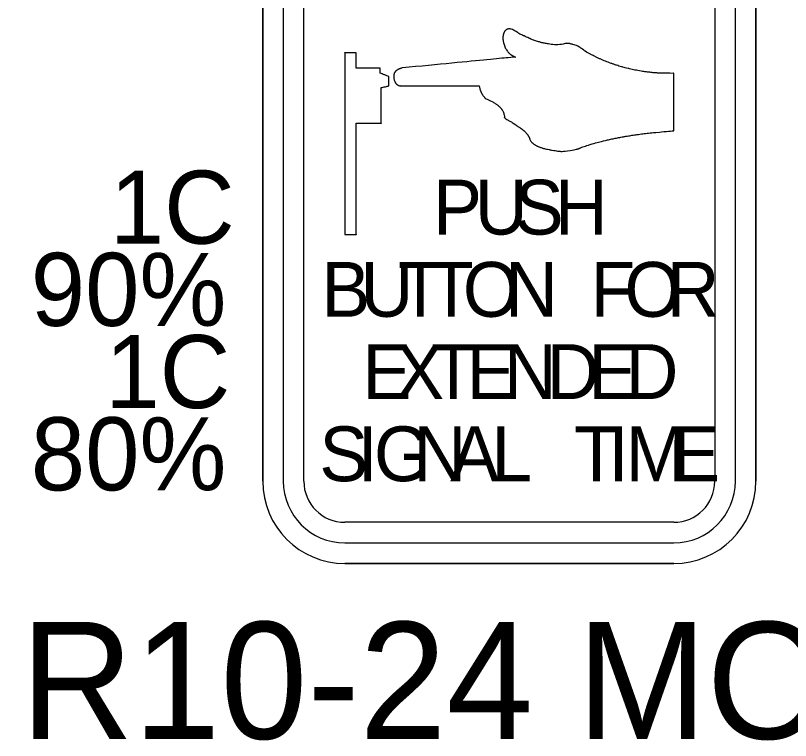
# Model space of a CAD drawing. Extents: x 99982 to 100176, y 99905 to 100011.
# Drawn here: x 100049.2714 to 100049.7487, y 99915.0774 to 99915.5238 of the extents above; entities that cross this region are included whole.
import ezdxf

# ---------------------------------------------------------------- set-up
doc = ezdxf.new("R2010")
doc.units = 0
doc.layers.add('TR_SN_ConstructionSigns', color=7, linetype='Continuous')

msp = doc.modelspace()

# ---------------------------------------------------------------- linework, layer by layer
at = {"layer": 'TR_SN_ConstructionSigns'}
for p, q in [((100049.42363, 99915.23704), (100049.42363, 99915.64204)), ((100049.42363, 99915.64204), (100049.42363, 99915.23704)), ((100049.42363, 99915.64204), (100049.42363, 99915.23704)), ((100049.43628, 99915.64204), (100049.43628, 99915.23704)), ((100049.44894, 99915.23704), (100049.44894, 99915.64204)), ((100049.70207, 99915.64204), (100049.70207, 99915.23704)), ((100049.71472, 99915.23704), (100049.71472, 99915.64204)), ((100049.72738, 99915.64204), (100049.72738, 99915.23704)), ((100049.72738, 99915.23704), (100049.72738, 99915.64204)), ((100049.72738, 99915.23704), (100049.72738, 99915.64204)), ((100049.67675, 99915.21173), (100049.47425, 99915.21173)), ((100049.47425, 99915.19907), (100049.67675, 99915.19907)), ((100049.67675, 99915.18641), (100049.47425, 99915.18641)), ((100049.47425, 99915.18641), (100049.67675, 99915.18641)), ((100049.47425, 99915.18641), (100049.67675, 99915.18641))]:
    msp.add_line(p, q, dxfattribs=at)
for centre, radius, start, end in [((100049.47425, 99915.23704), 0.05063, 180, 270), ((100049.47425, 99915.23704), 0.05063, 180, 270), ((100049.47425, 99915.23704), 0.05063, 180, 270), ((100049.47425, 99915.23704), 0.03797, 180, 270), ((100049.47425, 99915.23704), 0.02531, 180, 270), ((100049.67675, 99915.23704), 0.05063, 270, 0), ((100049.67675, 99915.23704), 0.05063, 270, 0), ((100049.67675, 99915.23704), 0.03797, 270, 0), ((100049.67675, 99915.23704), 0.02531, 270, 0), ((100049.67675, 99915.23704), 0.05063, 270, 0)]:
    msp.add_arc(centre, radius, start, end, dxfattribs=at)
for points, degree in [([(100049.5728, 99915.51427), (100049.5728, 99915.51427), (100049.57265, 99915.51408), (100049.57249, 99915.51386), (100049.5724, 99915.51369), (100049.5724, 99915.51369)], 3), ([(100049.57333, 99915.51481), (100049.57333, 99915.51481), (100049.57315, 99915.51466), (100049.57295, 99915.51446), (100049.5728, 99915.51427), (100049.5728, 99915.51427)], 3), ([(100049.57387, 99915.51516), (100049.57387, 99915.51516), (100049.5737, 99915.51507), (100049.57351, 99915.51496), (100049.57333, 99915.51481), (100049.57333, 99915.51481)], 3), ([(100049.57434, 99915.51535), (100049.57434, 99915.51535), (100049.5741, 99915.51527), (100049.57404, 99915.51524), (100049.57387, 99915.51516), (100049.57387, 99915.51516)], 3), ([(100049.57635, 99915.51548), (100049.57635, 99915.51548), (100049.57536, 99915.51564), (100049.57458, 99915.51543), (100049.57434, 99915.51535), (100049.57434, 99915.51535)], 3), ([(100049.58098, 99915.51302), (100049.58098, 99915.51302), (100049.57973, 99915.5138), (100049.57734, 99915.51531), (100049.57635, 99915.51548), (100049.57635, 99915.51548)], 3), ([(100049.57161, 99915.51109), (100049.57161, 99915.51109), (100049.57152, 99915.51049), (100049.57152, 99915.50963), (100049.5716, 99915.50894), (100049.5716, 99915.50894)], 3), ([(100049.57196, 99915.51252), (100049.57196, 99915.51252), (100049.57184, 99915.51216), (100049.57169, 99915.51168), (100049.57161, 99915.51109), (100049.57161, 99915.51109)], 3), ([(100049.57223, 99915.5133), (100049.57223, 99915.5133), (100049.57216, 99915.5131), (100049.57208, 99915.51288), (100049.57196, 99915.51252), (100049.57196, 99915.51252)], 3), ([(100049.5724, 99915.51369), (100049.5724, 99915.51369), (100049.57232, 99915.51353), (100049.57231, 99915.51349), (100049.57223, 99915.5133), (100049.57223, 99915.5133)], 3), ([(100049.58421, 99915.51137), (100049.58421, 99915.51137), (100049.58305, 99915.51191), (100049.58224, 99915.51224), (100049.58098, 99915.51302), (100049.58098, 99915.51302)], 3), ([(100049.58787, 99915.50971), (100049.58787, 99915.50971), (100049.58679, 99915.51017), (100049.58537, 99915.51084), (100049.58421, 99915.51137), (100049.58421, 99915.51137)], 3), ([(100049.59068, 99915.50859), (100049.59068, 99915.50859), (100049.5897, 99915.50895), (100049.58895, 99915.50925), (100049.58787, 99915.50971), (100049.58787, 99915.50971)], 3), ([(100049.5716, 99915.50894), (100049.5716, 99915.50894), (100049.57168, 99915.50825), (100049.57188, 99915.50737), (100049.57198, 99915.50697), (100049.57198, 99915.50697)], 3), ([(100049.57198, 99915.50697), (100049.57198, 99915.50697), (100049.57208, 99915.50657), (100049.57211, 99915.50648), (100049.57221, 99915.50617), (100049.57221, 99915.50617)], 3), ([(100049.57221, 99915.50617), (100049.57221, 99915.50617), (100049.5723, 99915.50586), (100049.57246, 99915.50546), (100049.57257, 99915.50511), (100049.57257, 99915.50511)], 3), ([(100049.57257, 99915.50511), (100049.57257, 99915.50511), (100049.57268, 99915.50476), (100049.57269, 99915.50458), (100049.57289, 99915.50408), (100049.57289, 99915.50408)], 3), ([(100049.59377, 99915.50756), (100049.59377, 99915.50756), (100049.59292, 99915.50782), (100049.59166, 99915.50823), (100049.59068, 99915.50859), (100049.59068, 99915.50859)], 3), ([(100049.59576, 99915.50701), (100049.59576, 99915.50701), (100049.59506, 99915.50719), (100049.59462, 99915.50731), (100049.59377, 99915.50756), (100049.59377, 99915.50756)], 3), ([(100049.59799, 99915.50653), (100049.59799, 99915.50653), (100049.597, 99915.50672), (100049.59647, 99915.50684), (100049.59576, 99915.50701), (100049.59576, 99915.50701)], 3), ([(100049.60176, 99915.50597), (100049.60176, 99915.50597), (100049.60025, 99915.50614), (100049.59899, 99915.50635), (100049.59799, 99915.50653), (100049.59799, 99915.50653)], 3), ([(100049.60704, 99915.50592), (100049.60704, 99915.50592), (100049.60536, 99915.50565), (100049.60326, 99915.50579), (100049.60176, 99915.50597), (100049.60176, 99915.50597)], 3), ([(100049.61195, 99915.50661), (100049.61195, 99915.50661), (100049.61098, 99915.50674), (100049.60873, 99915.5062), (100049.60704, 99915.50592), (100049.60704, 99915.50592)], 3), ([(100049.61384, 99915.50612), (100049.61384, 99915.50612), (100049.61295, 99915.50638), (100049.61292, 99915.50648), (100049.61195, 99915.50661), (100049.61195, 99915.50661)], 3), ([(100049.61732, 99915.50507), (100049.61732, 99915.50507), (100049.61594, 99915.50568), (100049.61474, 99915.50586), (100049.61384, 99915.50612), (100049.61384, 99915.50612)], 3), ([(100049.62181, 99915.50207), (100049.62181, 99915.50207), (100049.62044, 99915.50301), (100049.6187, 99915.50447), (100049.61732, 99915.50507), (100049.61732, 99915.50507)], 3), ([(100049.47425, 99915.50079), (100049.47425, 99915.50079), (100049.47425, 99915.50079), (100049.47425, 99915.38891)], 2), ([(100049.48122, 99915.50079), (100049.48122, 99915.50079), (100049.48122, 99915.50079), (100049.47425, 99915.50079)], 2), ([(100049.48122, 99915.49134), (100049.48122, 99915.49134), (100049.48122, 99915.49134), (100049.48122, 99915.50079)], 2), ([(100049.57289, 99915.50408), (100049.57289, 99915.50408), (100049.57309, 99915.50357), (100049.57384, 99915.50252), (100049.57424, 99915.50195), (100049.57424, 99915.50195)], 3), ([(100049.57424, 99915.50195), (100049.57424, 99915.50195), (100049.57465, 99915.50138), (100049.5749, 99915.50098), (100049.57526, 99915.50064), (100049.57526, 99915.50064)], 3), ([(100049.57526, 99915.50064), (100049.57526, 99915.50064), (100049.57562, 99915.5003), (100049.57596, 99915.5001), (100049.5763, 99915.49983), (100049.5763, 99915.49983)], 3), ([(100049.5763, 99915.49983), (100049.5763, 99915.49983), (100049.57664, 99915.49955), (100049.57687, 99915.49927), (100049.57738, 99915.49909), (100049.57738, 99915.49909)], 3), ([(100049.62576, 99915.49983), (100049.62576, 99915.49983), (100049.62461, 99915.50043), (100049.62318, 99915.50114), (100049.62181, 99915.50207), (100049.62181, 99915.50207)], 3), ([(100049.62865, 99915.49833), (100049.62865, 99915.49833), (100049.6275, 99915.4989), (100049.62692, 99915.49923), (100049.62576, 99915.49983), (100049.62576, 99915.49983)], 3), ([(100049.57905, 99915.49821), (100049.57905, 99915.49821), (100049.57905, 99915.49821), (100049.50981, 99915.49152)], 2), ([(100049.57738, 99915.49909), (100049.57738, 99915.49909), (100049.57789, 99915.49891), (100049.57913, 99915.49835), (100049.57913, 99915.4983), (100049.57913, 99915.4983)], 3), ([(100049.57913, 99915.49821), (100049.57913, 99915.49821), (100049.57913, 99915.49818), (100049.57905, 99915.49821), (100049.57905, 99915.49821)], 3), ([(100049.57913, 99915.4983), (100049.57913, 99915.4983), (100049.57913, 99915.49826), (100049.57913, 99915.49824), (100049.57913, 99915.49821), (100049.57913, 99915.49821)], 3), ([(100049.63274, 99915.49647), (100049.63274, 99915.49647), (100049.63137, 99915.49705), (100049.62981, 99915.49775), (100049.62865, 99915.49833), (100049.62865, 99915.49833)], 3), ([(100049.63683, 99915.49481), (100049.63683, 99915.49481), (100049.63544, 99915.49533), (100049.6341, 99915.49588), (100049.63274, 99915.49647), (100049.63274, 99915.49647)], 3), ([(100049.64108, 99915.49331), (100049.64108, 99915.49331), (100049.63973, 99915.49375), (100049.63822, 99915.49428), (100049.63683, 99915.49481), (100049.63683, 99915.49481)], 3), ([(100049.49601, 99915.49134), (100049.49601, 99915.49134), (100049.49601, 99915.49134), (100049.48122, 99915.49134)], 2), ([(100049.49601, 99915.4882), (100049.49601, 99915.4882), (100049.49601, 99915.4882), (100049.49601, 99915.49134)], 2), ([(100049.50667, 99915.49041), (100049.50667, 99915.49041), (100049.50633, 99915.49021), (100049.50596, 99915.48994), (100049.5057, 99915.48968), (100049.5057, 99915.48968)], 3), ([(100049.50769, 99915.49091), (100049.50769, 99915.49091), (100049.50735, 99915.49078), (100049.507, 99915.49061), (100049.50667, 99915.49041), (100049.50667, 99915.49041)], 3), ([(100049.50865, 99915.49125), (100049.50865, 99915.49125), (100049.50833, 99915.49115), (100049.50802, 99915.49105), (100049.50769, 99915.49091), (100049.50769, 99915.49091)], 3), ([(100049.50981, 99915.49152), (100049.50981, 99915.49152), (100049.50981, 99915.49152), (100049.50897, 99915.49136), (100049.50865, 99915.49125)], 3), ([(100049.64492, 99915.49214), (100049.64492, 99915.49214), (100049.6436, 99915.49251), (100049.64243, 99915.49287), (100049.64108, 99915.49331), (100049.64108, 99915.49331)], 3), ([(100049.64902, 99915.49107), (100049.64902, 99915.49107), (100049.64763, 99915.49141), (100049.64625, 99915.49176), (100049.64492, 99915.49214), (100049.64492, 99915.49214)], 3), ([(100049.65329, 99915.49014), (100049.65329, 99915.49014), (100049.65182, 99915.49043), (100049.65042, 99915.49074), (100049.64902, 99915.49107), (100049.64902, 99915.49107)], 3), ([(100049.65787, 99915.48935), (100049.65787, 99915.48935), (100049.65659, 99915.48955), (100049.65477, 99915.48985), (100049.65329, 99915.49014), (100049.65329, 99915.49014)], 3), ([(100049.49604, 99915.48826), (100049.49604, 99915.48826), (100049.49604, 99915.48826), (100049.49601, 99915.4882)], 2), ([(100049.49604, 99915.48826), (100049.49604, 99915.48826), (100049.49604, 99915.48826), (100049.49601, 99915.4882)], 2), ([(100049.50132, 99915.48619), (100049.50132, 99915.48619), (100049.50132, 99915.48619), (100049.49604, 99915.48826)], 2), ([(100049.50139, 99915.48044), (100049.50139, 99915.48044), (100049.50139, 99915.48044), (100049.50132, 99915.48619)], 2), ([(100049.50444, 99915.48763), (100049.50444, 99915.48763), (100049.50433, 99915.48718), (100049.5043, 99915.48579), (100049.50443, 99915.48505), (100049.50443, 99915.48505)], 3), ([(100049.50478, 99915.48848), (100049.50478, 99915.48848), (100049.50466, 99915.48827), (100049.50456, 99915.48807), (100049.50444, 99915.48763), (100049.50444, 99915.48763)], 3), ([(100049.50507, 99915.48893), (100049.50507, 99915.48893), (100049.50492, 99915.48872), (100049.5049, 99915.48869), (100049.50478, 99915.48848), (100049.50478, 99915.48848)], 3), ([(100049.5057, 99915.48968), (100049.5057, 99915.48968), (100049.50544, 99915.48943), (100049.50522, 99915.48914), (100049.50507, 99915.48893), (100049.50507, 99915.48893)], 3), ([(100049.66091, 99915.48893), (100049.66091, 99915.48893), (100049.65981, 99915.48907), (100049.65914, 99915.48916), (100049.65787, 99915.48935), (100049.65787, 99915.48935)], 3), ([(100049.66444, 99915.48856), (100049.66444, 99915.48856), (100049.66342, 99915.48865), (100049.662, 99915.48879), (100049.66091, 99915.48893), (100049.66091, 99915.48893)], 3), ([(100049.66702, 99915.48837), (100049.66702, 99915.48837), (100049.66616, 99915.48843), (100049.66546, 99915.48848), (100049.66444, 99915.48856), (100049.66444, 99915.48856)], 3), ([(100049.67661, 99915.48816), (100049.67661, 99915.48816), (100049.67661, 99915.48816), (100049.66788, 99915.48831), (100049.66702, 99915.48837)], 3), ([(100049.67675, 99915.48834), (100049.67675, 99915.48834), (100049.67675, 99915.48834), (100049.67661, 99915.48816)], 2), ([(100049.67675, 99915.45279), (100049.67675, 99915.45279), (100049.67675, 99915.45279), (100049.67675, 99915.48834)], 2), ([(100049.49658, 99915.47936), (100049.49658, 99915.47936), (100049.49658, 99915.47936), (100049.50139, 99915.48044)], 2), ([(100049.50443, 99915.48505), (100049.50443, 99915.48505), (100049.50455, 99915.48431), (100049.50481, 99915.4835), (100049.50494, 99915.4832), (100049.50494, 99915.4832)], 3), ([(100049.50494, 99915.4832), (100049.50494, 99915.4832), (100049.50507, 99915.48291), (100049.50511, 99915.48283), (100049.50522, 99915.48263), (100049.50522, 99915.48263)], 3), ([(100049.50522, 99915.48263), (100049.50522, 99915.48263), (100049.50532, 99915.48243), (100049.50546, 99915.48217), (100049.50559, 99915.482), (100049.50559, 99915.482)], 3), ([(100049.50559, 99915.482), (100049.50559, 99915.482), (100049.50572, 99915.48183), (100049.50577, 99915.48178), (100049.50597, 99915.48159), (100049.50597, 99915.48159)], 3), ([(100049.50597, 99915.48159), (100049.50597, 99915.48159), (100049.50618, 99915.48141), (100049.50654, 99915.48113), (100049.50684, 99915.48092), (100049.50684, 99915.48092)], 3), ([(100049.50684, 99915.48092), (100049.50684, 99915.48092), (100049.50714, 99915.48071), (100049.5082, 99915.48051), (100049.5082, 99915.48051)], 3), ([(100049.5082, 99915.48051), (100049.5082, 99915.48051), (100049.5082, 99915.48051), (100049.55695, 99915.48044)], 2), ([(100049.55695, 99915.48044), (100049.55695, 99915.48044), (100049.55695, 99915.48044), (100049.55741, 99915.47844), (100049.55753, 99915.4781)], 3), ([(100049.49659, 99915.45744), (100049.49659, 99915.45744), (100049.49659, 99915.45744), (100049.49658, 99915.47936)], 2), ([(100049.55753, 99915.4781), (100049.55753, 99915.4781), (100049.55765, 99915.47777), (100049.55776, 99915.47744), (100049.5579, 99915.4771), (100049.5579, 99915.4771)], 3), ([(100049.5579, 99915.4771), (100049.5579, 99915.4771), (100049.55804, 99915.47675), (100049.55822, 99915.47637), (100049.5584, 99915.47603), (100049.5584, 99915.47603)], 3), ([(100049.5584, 99915.47603), (100049.5584, 99915.47603), (100049.55859, 99915.47569), (100049.55874, 99915.47545), (100049.559, 99915.47507), (100049.559, 99915.47507)], 3), ([(100049.559, 99915.47507), (100049.559, 99915.47507), (100049.55926, 99915.47469), (100049.55971, 99915.47407), (100049.55995, 99915.47375), (100049.55995, 99915.47375)], 3), ([(100049.55995, 99915.47375), (100049.55995, 99915.47375), (100049.56018, 99915.47342), (100049.56017, 99915.47341), (100049.56044, 99915.47311), (100049.56044, 99915.47311)], 3), ([(100049.56044, 99915.47311), (100049.56044, 99915.47311), (100049.5607, 99915.47281), (100049.56467, 99915.47083), (100049.56558, 99915.47037), (100049.56558, 99915.47037)], 3), ([(100049.56558, 99915.47037), (100049.56558, 99915.47037), (100049.56648, 99915.4699), (100049.56678, 99915.46966), (100049.5673, 99915.46929), (100049.5673, 99915.46929)], 3), ([(100049.5673, 99915.46929), (100049.5673, 99915.46929), (100049.56782, 99915.46892), (100049.56835, 99915.4685), (100049.56873, 99915.46821), (100049.56873, 99915.46821)], 3), ([(100049.56873, 99915.46821), (100049.56873, 99915.46821), (100049.5691, 99915.46792), (100049.5693, 99915.46776), (100049.56953, 99915.46754), (100049.56953, 99915.46754)], 3), ([(100049.56953, 99915.46754), (100049.56953, 99915.46754), (100049.56977, 99915.46731), (100049.5699, 99915.46716), (100049.57015, 99915.46685), (100049.57015, 99915.46685)], 3), ([(100049.57015, 99915.46685), (100049.57015, 99915.46685), (100049.5704, 99915.46655), (100049.57076, 99915.4661), (100049.57103, 99915.4657), (100049.57103, 99915.4657)], 3), ([(100049.57103, 99915.4657), (100049.57103, 99915.4657), (100049.57131, 99915.4653), (100049.57164, 99915.46471), (100049.57175, 99915.46444), (100049.57175, 99915.46444)], 3), ([(100049.57175, 99915.46444), (100049.57175, 99915.46444), (100049.57187, 99915.46418), (100049.57189, 99915.46411), (100049.57196, 99915.46391), (100049.57196, 99915.46391)], 3), ([(100049.57196, 99915.46391), (100049.57196, 99915.46391), (100049.57203, 99915.46371), (100049.5721, 99915.46347), (100049.57217, 99915.46325), (100049.57217, 99915.46325)], 3), ([(100049.57217, 99915.46325), (100049.57217, 99915.46325), (100049.57224, 99915.46303), (100049.57262, 99915.46097), (100049.57262, 99915.46097)], 3), ([(100049.48122, 99915.45744), (100049.48122, 99915.45744), (100049.48122, 99915.45744), (100049.49659, 99915.45744)], 2), ([(100049.48122, 99915.38891), (100049.48122, 99915.38891), (100049.48122, 99915.38891), (100049.48122, 99915.45744)], 2), ([(100049.57262, 99915.46097), (100049.57262, 99915.46097), (100049.57262, 99915.46097), (100049.57239, 99915.46123), (100049.57244, 99915.46114)], 3), ([(100049.57244, 99915.46114), (100049.57244, 99915.46114), (100049.57249, 99915.46105), (100049.57251, 99915.461), (100049.5726, 99915.46087), (100049.5726, 99915.46087)], 3), ([(100049.5726, 99915.46087), (100049.5726, 99915.46087), (100049.57268, 99915.46073), (100049.57385, 99915.45979), (100049.57507, 99915.4592), (100049.57507, 99915.4592)], 3), ([(100049.57507, 99915.4592), (100049.57507, 99915.4592), (100049.57629, 99915.4586), (100049.57832, 99915.45721), (100049.57944, 99915.45644), (100049.57944, 99915.45644)], 3), ([(100049.57944, 99915.45644), (100049.57944, 99915.45644), (100049.58055, 99915.45567), (100049.58102, 99915.45537), (100049.58191, 99915.45477), (100049.58191, 99915.45477)], 3), ([(100049.58191, 99915.45477), (100049.58191, 99915.45477), (100049.58279, 99915.45418), (100049.5839, 99915.4534), (100049.58464, 99915.45271), (100049.58464, 99915.45271)], 3), ([(100049.58464, 99915.45271), (100049.58464, 99915.45271), (100049.58538, 99915.45202), (100049.58595, 99915.45131), (100049.5864, 99915.45073), (100049.5864, 99915.45073)], 3), ([(100049.66304, 99915.45158), (100049.66304, 99915.45158), (100049.66596, 99915.45192), (100049.67675, 99915.45279), (100049.67675, 99915.45279)], 3), ([(100049.5864, 99915.45073), (100049.5864, 99915.45073), (100049.58686, 99915.45015), (100049.58718, 99915.4497), (100049.58744, 99915.44929), (100049.58744, 99915.44929)], 3), ([(100049.58744, 99915.44929), (100049.58744, 99915.44929), (100049.5877, 99915.44889), (100049.58779, 99915.44875), (100049.58796, 99915.44829), (100049.58796, 99915.44829)], 3), ([(100049.58796, 99915.44829), (100049.58796, 99915.44829), (100049.58814, 99915.44783), (100049.58828, 99915.44706), (100049.58857, 99915.44657), (100049.58857, 99915.44657)], 3), ([(100049.6329, 99915.44644), (100049.6329, 99915.44644), (100049.63477, 99915.4469), (100049.63708, 99915.44744), (100049.63935, 99915.44791), (100049.63935, 99915.44791)], 3), ([(100049.63935, 99915.44791), (100049.63935, 99915.44791), (100049.64162, 99915.44839), (100049.64402, 99915.44885), (100049.64651, 99915.44928), (100049.64651, 99915.44928)], 3), ([(100049.64651, 99915.44928), (100049.64651, 99915.44928), (100049.649, 99915.44972), (100049.65153, 99915.45012), (100049.65429, 99915.4505), (100049.65429, 99915.4505)], 3), ([(100049.65429, 99915.4505), (100049.65429, 99915.4505), (100049.65704, 99915.45088), (100049.66012, 99915.45124), (100049.66304, 99915.45158), (100049.66304, 99915.45158)], 3), ([(100049.58857, 99915.44657), (100049.58857, 99915.44657), (100049.58886, 99915.44607), (100049.58932, 99915.44571), (100049.58968, 99915.44539), (100049.58968, 99915.44539)], 3), ([(100049.58968, 99915.44539), (100049.58968, 99915.44539), (100049.59005, 99915.44507), (100049.59025, 99915.44486), (100049.59066, 99915.44456), (100049.59066, 99915.44456)], 3), ([(100049.59066, 99915.44456), (100049.59066, 99915.44456), (100049.59107, 99915.44425), (100049.59167, 99915.4439), (100049.59219, 99915.44363), (100049.59219, 99915.44363)], 3), ([(100049.59219, 99915.44363), (100049.59219, 99915.44363), (100049.59272, 99915.44336), (100049.59316, 99915.44316), (100049.59378, 99915.44291), (100049.59378, 99915.44291)], 3), ([(100049.59378, 99915.44291), (100049.59378, 99915.44291), (100049.59439, 99915.44267), (100049.59507, 99915.44244), (100049.59589, 99915.4422), (100049.59589, 99915.4422)], 3), ([(100049.59589, 99915.4422), (100049.59589, 99915.4422), (100049.59671, 99915.44196), (100049.59744, 99915.44176), (100049.59868, 99915.44149), (100049.59868, 99915.44149)], 3), ([(100049.61812, 99915.44183), (100049.61812, 99915.44183), (100049.61853, 99915.44197), (100049.61883, 99915.44209), (100049.61954, 99915.44236), (100049.61954, 99915.44236)], 3), ([(100049.61954, 99915.44236), (100049.61954, 99915.44236), (100049.62025, 99915.44263), (100049.62131, 99915.44302), (100049.62274, 99915.4435), (100049.62274, 99915.4435)], 3), ([(100049.62274, 99915.4435), (100049.62274, 99915.4435), (100049.62417, 99915.44398), (100049.62644, 99915.44469), (100049.62814, 99915.44517), (100049.62814, 99915.44517)], 3), ([(100049.62814, 99915.44517), (100049.62814, 99915.44517), (100049.62983, 99915.44566), (100049.63104, 99915.44598), (100049.6329, 99915.44644), (100049.6329, 99915.44644)], 3), ([(100049.59868, 99915.44149), (100049.59868, 99915.44149), (100049.59993, 99915.44122), (100049.60193, 99915.44088), (100049.60337, 99915.44065), (100049.60337, 99915.44065)], 3), ([(100049.60337, 99915.44065), (100049.60337, 99915.44065), (100049.6048, 99915.44041), (100049.60531, 99915.44025), (100049.60729, 99915.44013), (100049.60729, 99915.44013)], 3), ([(100049.60729, 99915.44013), (100049.60729, 99915.44013), (100049.60927, 99915.44), (100049.61658, 99915.44136), (100049.6171, 99915.44151), (100049.6171, 99915.44151)], 3), ([(100049.6171, 99915.44151), (100049.6171, 99915.44151), (100049.61761, 99915.44166), (100049.61771, 99915.44169), (100049.61812, 99915.44183), (100049.61812, 99915.44183)], 3), ([(100049.47425, 99915.38891), (100049.47425, 99915.38891), (100049.47425, 99915.38891), (100049.48122, 99915.38891)], 2)]:
    msp.add_open_spline(points, degree=degree, dxfattribs=at)

# ---------------------------------------------------------------- texts
for s, height, p in [('1C', 0.045, (100049.32943, 99915.38329)), ('S', 0.03375, (100049.57888, 99915.38891)), ('P', 0.03375, (100049.52857, 99915.38891)), ('U', 0.03375, (100049.55424, 99915.38891)), ('H', 0.03375, (100049.60353, 99915.38891)), ('1C, 90%', 0.045, (100049.17043, 99915.33266)), ('B', 0.03375, (100049.45976, 99915.33829)), ('U', 0.03375, (100049.48382, 99915.33829)), ('T', 0.03375, (100049.50697, 99915.33829)), ('T', 0.03375, (100049.52601, 99915.33829)), ('O', 0.03375, (100049.54687, 99915.33829)), ('N', 0.03375, (100049.57285, 99915.33829)), ('F', 0.03375, (100049.6255, 99915.33829)), ('O', 0.03375, (100049.64636, 99915.33829)), ('R', 0.03375, (100049.67235, 99915.33829)), ('1C', 0.045, (100049.32672, 99915.28204)), ('E', 0.03375, (100049.48505, 99915.28766)), ('X', 0.03375, (100049.5053, 99915.28766)), ('T', 0.03375, (100049.52724, 99915.28766)), ('E', 0.03375, (100049.54918, 99915.28766)), ('N', 0.03375, (100049.57213, 99915.28766)), ('D', 0.03375, (100049.59845, 99915.28766)), ('E', 0.03375, (100049.6241, 99915.28766)), ('D', 0.03375, (100049.64705, 99915.28766)), ('1C, 80%', 0.045, (100049.17043, 99915.23141)), ('S', 0.03375, (100049.45849, 99915.23704)), ('I', 0.03375, (100049.48198, 99915.23704)), ('G', 0.03375, (100049.49211, 99915.23704)), ('N', 0.03375, (100049.51641, 99915.23704)), ('A', 0.03375, (100049.53909, 99915.23704)), ('L', 0.03375, (100049.56447, 99915.23704)), ('T', 0.03375, (100049.61543, 99915.23704)), ('I', 0.03375, (100049.63642, 99915.23704)), ('M', 0.03375, (100049.64709, 99915.23704)), ('E', 0.03375, (100049.6753, 99915.23704))]:
    msp.add_text(s, height=height, dxfattribs=at).set_placement(p)
msp.add_text('R10-24 MOD', height=0.072, rotation=360, dxfattribs=at).set_placement((100049.27452, 99915.07841))

doc.saveas('drawing.dxf')
